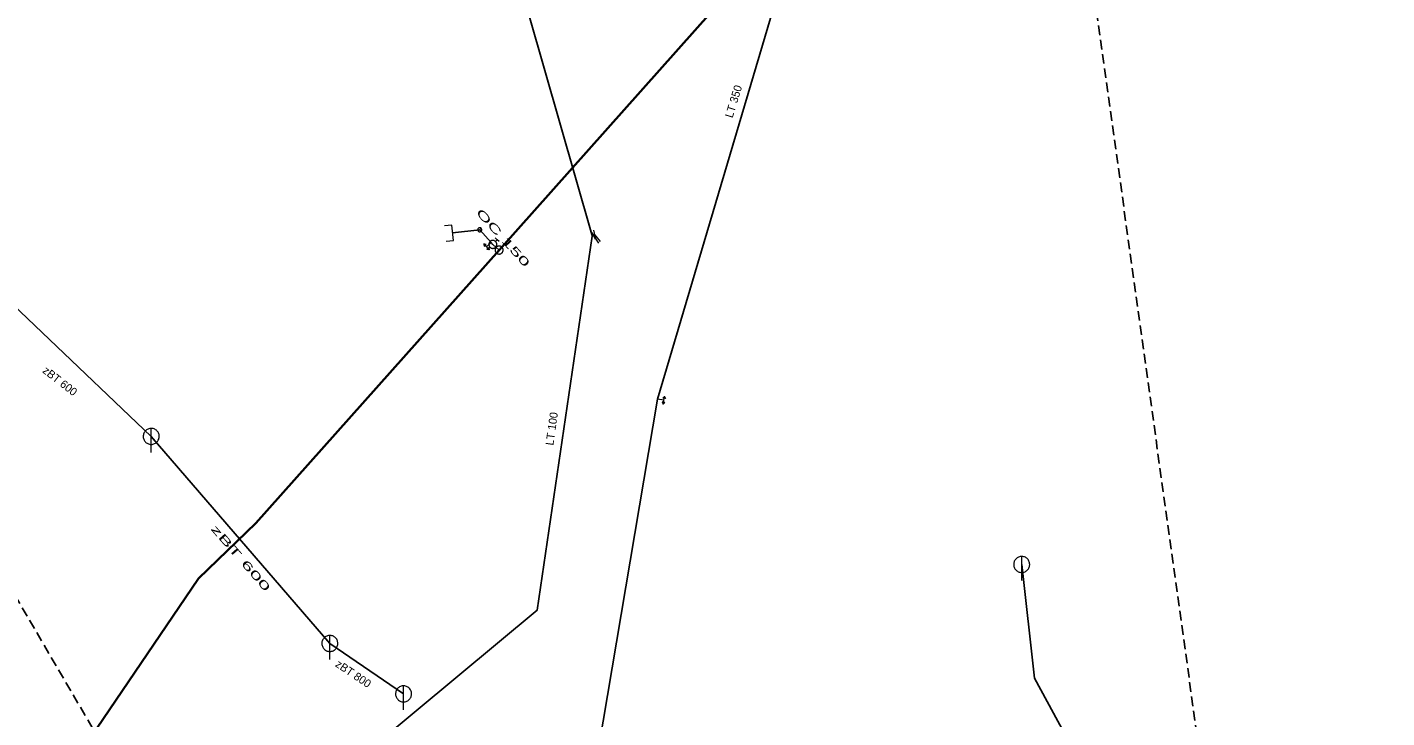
# Model space of a CAD drawing. Extents: x -687016 to -686065, y -974192 to -973552.
# Drawn here: x -686248.4 to -686078.5, y -973940.5 to -973854.3 of the extents above; entities that cross this region are included whole.
import ezdxf

# ---------------------------------------------------------------- set-up
doc = ezdxf.new("R2010")
doc.units = 0
doc.header["$LTSCALE"] = 0.4
doc.linetypes.add('MEDIUM_DASHED', pattern=[4.5, 3, -1.5])
doc.layers.add('1', color=7, linetype='Continuous')
for name, color, linetype, lineweight in [('13', 7, 'Continuous', 13), ('14', 7, 'Continuous', 25), ('17', 7, 'Continuous', 25), ('22', 7, 'Continuous', 13), ('23', 7, 'Continuous', 13), ('34', 7, 'Continuous', 13), ('42', 7, 'Continuous', 13), ('47', 7, 'Continuous', 13), ('63', 7, 'MEDIUM_DASHED', 25)]:
    doc.layers.add(name, color=color, linetype=linetype, lineweight=lineweight)

msp = doc.modelspace()

# ---------------------------------------------------------------- linework, layer by layer
at = {"layer": '13'}
for p, q in [((-686177.649, -973880.329), (-686177.02, -973881.28)), ((-686177.539, -973880.129), (-686176.82, -973881.05))]:
    msp.add_line(p, q, dxfattribs=at)
at = {"layer": '14', "lineweight": 13}
for p, q in [((-686177.867, -973880.202), (-686177.539, -973880.129)), ((-686177.797, -973880.398), (-686177.649, -973880.329)), ((-686190.215, -973881.425), (-686190.418, -973881.199))]:
    msp.add_line(p, q, dxfattribs=at)
at = {"layer": '14'}
for p, q in [((-686232.891, -973905.396), (-686251.059, -973888.086)), ((-686210.577, -973931.25), (-686232.891, -973905.396)), ((-686201.369, -973937.547), (-686210.577, -973931.25))]:
    msp.add_line(p, q, dxfattribs=at)
msp.add_lwpolyline([(-686124.153, -973921.386), (-686122.535, -973935.572), (-686106.927, -973964.355)], dxfattribs=at)
at = {"layer": '17'}
for p, q in [((-686147.316, -973825.46), (-686169.64, -973900.75)), ((-686189.43, -973882.125), (-686190.215, -973881.425))]:
    msp.add_line(p, q, dxfattribs=at)
at = {"layer": '17', "lineweight": 35}
for points in [[(-686163.783, -973551.821), (-686169.469, -973574.282), (-686122.999, -973646.384), (-686098.932, -973712.353), (-686078.54, -973769.323), (-686149.348, -973837.164), (-686189.43, -973882.125)], [(-686189.43, -973882.125), (-686219.828, -973916.223), (-686226.999, -973923.155), (-686246.828, -973952.39), (-686262.803, -973979.756), (-686282.183, -974011.51), (-686299.629, -974035.3), (-686327.833, -974075.543), (-686339.475, -974087.052), (-686408.796, -974118.009)]]:
    msp.add_lwpolyline(points, dxfattribs=at)
at = {"layer": '17'}
for points in [[(-686204.755, -973943.783), (-686184.694, -973927.101), (-686177.797, -973880.398), (-686177.867, -973880.202), (-686191.62, -973832.066)], [(-686190.418, -973881.199), (-686191.853, -973879.59), (-686195.24, -973879.96)], [(-686169.64, -973900.75), (-686177.013, -973944.41), (-686197.048, -973943.572), (-686232.018, -974032.331), (-686151.042, -974110.8), (-686189.024, -974153.642), (-686204.782, -974140.962), (-686246.709, -974191.881)]]:
    msp.add_lwpolyline(points, dxfattribs=at)
at = {"layer": '22'}
for p, q in [((-686232.891, -973907.396), (-686232.89, -973904.396)), ((-686124.153, -973923.387), (-686124.152, -973920.387)), ((-686210.577, -973933.25), (-686210.576, -973930.25)), ((-686201.369, -973939.547), (-686201.368, -973936.547))]:
    msp.add_line(p, q, dxfattribs=at)
for points in [[(-686231.891, -973905.396), (-686231.896, -973905.287), (-686231.914, -973905.179), (-686231.944, -973905.073), (-686231.984, -973904.972), (-686232.036, -973904.875), (-686232.098, -973904.785), (-686232.17, -973904.702), (-686232.25, -973904.628), (-686232.338, -973904.562), (-686232.432, -973904.507), (-686232.532, -973904.462), (-686232.637, -973904.429), (-686232.744, -973904.407), (-686232.853, -973904.397), (-686232.963, -973904.399), (-686233.071, -973904.413), (-686233.178, -973904.438), (-686233.281, -973904.475), (-686233.379, -973904.524), (-686233.471, -973904.582), (-686233.557, -973904.651), (-686233.634, -973904.728), (-686233.703, -973904.814), (-686233.762, -973904.906), (-686233.81, -973905.004), (-686233.847, -973905.107), (-686233.873, -973905.214), (-686233.887, -973905.322), (-686233.89, -973905.432), (-686233.88, -973905.541), (-686233.859, -973905.648), (-686233.825, -973905.752), (-686233.781, -973905.852), (-686233.726, -973905.947), (-686233.66, -973906.035), (-686233.586, -973906.115), (-686233.503, -973906.187), (-686233.413, -973906.249), (-686233.317, -973906.301), (-686233.215, -973906.342), (-686233.11, -973906.372), (-686233.002, -973906.39), (-686232.892, -973906.396), (-686232.783, -973906.39), (-686232.675, -973906.372), (-686232.57, -973906.343), (-686232.468, -973906.302), (-686232.371, -973906.25), (-686232.281, -973906.188), (-686232.198, -973906.117), (-686232.123, -973906.037), (-686232.058, -973905.949), (-686232.002, -973905.855), (-686231.958, -973905.755), (-686231.924, -973905.651), (-686231.902, -973905.543), (-686231.892, -973905.434)], [(-686123.153, -973921.387), (-686123.158, -973921.278), (-686123.176, -973921.17), (-686123.206, -973921.064), (-686123.246, -973920.963), (-686123.298, -973920.866), (-686123.36, -973920.776), (-686123.432, -973920.693), (-686123.512, -973920.619), (-686123.6, -973920.553), (-686123.694, -973920.498), (-686123.794, -973920.453), (-686123.899, -973920.42), (-686124.006, -973920.398), (-686124.115, -973920.388), (-686124.225, -973920.39), (-686124.333, -973920.404), (-686124.44, -973920.429), (-686124.543, -973920.466), (-686124.641, -973920.515), (-686124.733, -973920.573), (-686124.819, -973920.642), (-686124.896, -973920.719), (-686124.965, -973920.805), (-686125.024, -973920.897), (-686125.072, -973920.995), (-686125.109, -973921.098), (-686125.135, -973921.205), (-686125.149, -973921.313), (-686125.152, -973921.423), (-686125.142, -973921.532), (-686125.121, -973921.639), (-686125.087, -973921.743), (-686125.043, -973921.843), (-686124.988, -973921.938), (-686124.922, -973922.026), (-686124.848, -973922.106), (-686124.765, -973922.178), (-686124.675, -973922.24), (-686124.579, -973922.292), (-686124.477, -973922.333), (-686124.372, -973922.363), (-686124.264, -973922.381), (-686124.154, -973922.387), (-686124.045, -973922.381), (-686123.937, -973922.363), (-686123.832, -973922.334), (-686123.73, -973922.293), (-686123.633, -973922.241), (-686123.543, -973922.179), (-686123.46, -973922.108), (-686123.385, -973922.028), (-686123.32, -973921.94), (-686123.264, -973921.846), (-686123.22, -973921.746), (-686123.186, -973921.642), (-686123.164, -973921.534), (-686123.154, -973921.425)], [(-686209.577, -973931.25), (-686209.582, -973931.141), (-686209.6, -973931.033), (-686209.63, -973930.927), (-686209.67, -973930.826), (-686209.722, -973930.729), (-686209.784, -973930.639), (-686209.856, -973930.556), (-686209.936, -973930.482), (-686210.024, -973930.416), (-686210.118, -973930.361), (-686210.218, -973930.316), (-686210.323, -973930.283), (-686210.43, -973930.261), (-686210.539, -973930.251), (-686210.649, -973930.253), (-686210.757, -973930.267), (-686210.864, -973930.292), (-686210.967, -973930.329), (-686211.065, -973930.378), (-686211.157, -973930.436), (-686211.243, -973930.505), (-686211.32, -973930.582), (-686211.389, -973930.668), (-686211.448, -973930.76), (-686211.496, -973930.858), (-686211.533, -973930.961), (-686211.559, -973931.068), (-686211.573, -973931.176), (-686211.576, -973931.286), (-686211.566, -973931.395), (-686211.545, -973931.502), (-686211.511, -973931.606), (-686211.467, -973931.706), (-686211.412, -973931.801), (-686211.346, -973931.889), (-686211.272, -973931.969), (-686211.189, -973932.041), (-686211.099, -973932.103), (-686211.003, -973932.155), (-686210.901, -973932.196), (-686210.796, -973932.226), (-686210.688, -973932.244), (-686210.578, -973932.25), (-686210.469, -973932.244), (-686210.361, -973932.226), (-686210.256, -973932.197), (-686210.154, -973932.156), (-686210.057, -973932.104), (-686209.967, -973932.042), (-686209.884, -973931.971), (-686209.809, -973931.891), (-686209.744, -973931.803), (-686209.688, -973931.709), (-686209.644, -973931.609), (-686209.61, -973931.505), (-686209.588, -973931.397), (-686209.578, -973931.288)], [(-686200.369, -973937.547), (-686200.374, -973937.438), (-686200.392, -973937.33), (-686200.422, -973937.224), (-686200.462, -973937.123), (-686200.514, -973937.026), (-686200.576, -973936.936), (-686200.648, -973936.853), (-686200.728, -973936.779), (-686200.816, -973936.713), (-686200.91, -973936.658), (-686201.01, -973936.613), (-686201.115, -973936.58), (-686201.222, -973936.558), (-686201.331, -973936.548), (-686201.441, -973936.55), (-686201.549, -973936.564), (-686201.656, -973936.589), (-686201.759, -973936.626), (-686201.857, -973936.675), (-686201.949, -973936.733), (-686202.035, -973936.802), (-686202.112, -973936.879), (-686202.181, -973936.965), (-686202.24, -973937.057), (-686202.288, -973937.155), (-686202.325, -973937.258), (-686202.351, -973937.365), (-686202.365, -973937.473), (-686202.368, -973937.583), (-686202.358, -973937.692), (-686202.337, -973937.799), (-686202.303, -973937.903), (-686202.259, -973938.003), (-686202.204, -973938.098), (-686202.138, -973938.186), (-686202.064, -973938.266), (-686201.981, -973938.338), (-686201.891, -973938.4), (-686201.795, -973938.452), (-686201.693, -973938.493), (-686201.588, -973938.523), (-686201.48, -973938.541), (-686201.37, -973938.547), (-686201.261, -973938.541), (-686201.153, -973938.523), (-686201.048, -973938.494), (-686200.946, -973938.453), (-686200.849, -973938.401), (-686200.759, -973938.339), (-686200.676, -973938.268), (-686200.601, -973938.188), (-686200.536, -973938.1), (-686200.48, -973938.006), (-686200.436, -973937.906), (-686200.402, -973937.802), (-686200.38, -973937.694), (-686200.37, -973937.585)]]:
    msp.add_lwpolyline(points, close=True, dxfattribs=at)
at = {"layer": '23'}
for p, q in [((-686192.04, -973879.758), (-686191.657, -973879.415)), ((-686189.943, -973880.608), (-686189.688, -973880.835)), ((-686189.873, -973881.043), (-686189.688, -973880.835)), ((-686189.432, -973881.063), (-686189.688, -973880.835))]:
    msp.add_line(p, q, dxfattribs=at)
for points in [[(-686192.018, -973879.401), (-686192.037, -973879.42), (-686192.055, -973879.44), (-686192.069, -973879.461), (-686192.081, -973879.484), (-686192.092, -973879.509), (-686192.098, -973879.535), (-686192.103, -973879.561), (-686192.105, -973879.586), (-686192.104, -973879.613), (-686192.099, -973879.639), (-686192.092, -973879.665), (-686192.084, -973879.689), (-686192.071, -973879.714), (-686192.057, -973879.735), (-686192.041, -973879.755), (-686192.022, -973879.774), (-686192.002, -973879.792), (-686191.981, -973879.806), (-686191.957, -973879.818), (-686191.932, -973879.829), (-686191.907, -973879.835), (-686191.881, -973879.839), (-686191.855, -973879.842), (-686191.829, -973879.84), (-686191.803, -973879.836), (-686191.777, -973879.829), (-686191.752, -973879.821), (-686191.728, -973879.809), (-686191.706, -973879.794), (-686191.686, -973879.778), (-686191.667, -973879.76), (-686191.65, -973879.74), (-686191.635, -973879.718), (-686191.623, -973879.694), (-686191.613, -973879.669), (-686191.607, -973879.644), (-686191.602, -973879.618), (-686191.599, -973879.592), (-686191.601, -973879.566), (-686191.606, -973879.539), (-686191.612, -973879.514), (-686191.621, -973879.488), (-686191.633, -973879.465), (-686191.647, -973879.443), (-686191.663, -973879.423), (-686191.682, -973879.404), (-686191.701, -973879.387), (-686191.724, -973879.372), (-686191.747, -973879.361), (-686191.773, -973879.35), (-686191.798, -973879.343), (-686191.824, -973879.339), (-686191.849, -973879.336), (-686191.876, -973879.338), (-686191.903, -973879.343), (-686191.928, -973879.349), (-686191.953, -973879.358), (-686191.976, -973879.371), (-686191.998, -973879.385)], [(-686189.847, -973881.758), (-686189.814, -973881.716), (-686189.784, -973881.674), (-686189.761, -973881.625), (-686189.743, -973881.578), (-686189.729, -973881.53), (-686189.721, -973881.477), (-686189.72, -973881.426), (-686189.721, -973881.372), (-686189.728, -973881.322), (-686189.743, -973881.272), (-686189.761, -973881.224), (-686189.785, -973881.179), (-686189.813, -973881.133), (-686189.845, -973881.093), (-686189.881, -973881.057), (-686189.921, -973881.025), (-686189.965, -973880.998), (-686190.011, -973880.973), (-686190.059, -973880.954), (-686190.111, -973880.94), (-686190.16, -973880.932), (-686190.214, -973880.929), (-686190.264, -973880.932), (-686190.317, -973880.941), (-686190.367, -973880.953), (-686190.415, -973880.97), (-686190.461, -973880.994), (-686190.506, -973881.022), (-686190.544, -973881.056), (-686190.584, -973881.093), (-686190.616, -973881.133), (-686190.643, -973881.177), (-686190.668, -973881.223), (-686190.687, -973881.271), (-686190.699, -973881.32), (-686190.709, -973881.372), (-686190.71, -973881.423), (-686190.709, -973881.476), (-686190.7, -973881.528), (-686190.686, -973881.577), (-686190.666, -973881.626), (-686190.645, -973881.674), (-686190.617, -973881.715), (-686190.582, -973881.758), (-686190.546, -973881.794), (-686190.506, -973881.825), (-686190.464, -973881.855), (-686190.416, -973881.878), (-686190.368, -973881.896), (-686190.317, -973881.91), (-686190.267, -973881.918), (-686190.214, -973881.921), (-686190.163, -973881.918), (-686190.113, -973881.911), (-686190.062, -973881.896), (-686190.012, -973881.88), (-686189.967, -973881.856), (-686189.924, -973881.826), (-686189.883, -973881.794)]]:
    msp.add_lwpolyline(points, close=True, dxfattribs=at)
at = {"layer": '34'}
for p, q in [((-686177.859, -973879.875), (-686177.439, -973880.783)), ((-686177.647, -973879.64), (-686177.431, -973880.617)), ((-686191.342, -973881.389), (-686191.318, -973881.368)), ((-686191.334, -973881.421), (-686191.287, -973881.378)), ((-686191.332, -973881.451), (-686191.256, -973881.383)), ((-686191.328, -973881.479), (-686191.229, -973881.389)), ((-686191.321, -973881.51), (-686191.198, -973881.398)), ((-686191.318, -973881.538), (-686191.172, -973881.405)), ((-686191.312, -973881.566), (-686191.144, -973881.412)), ((-686191.311, -973881.598), (-686191.113, -973881.417)), ((-686191.304, -973881.628), (-686191.083, -973881.427)), ((-686191.015, -973881.731), (-686190.418, -973881.199)), ((-686190.945, -973882.031), (-686190.72, -973881.834)), ((-686190.916, -973882.041), (-686190.714, -973881.865)), ((-686190.885, -973882.046), (-686190.713, -973881.896)), ((-686190.857, -973882.054), (-686190.709, -973881.925)), ((-686190.83, -973882.061), (-686190.704, -973881.952)), ((-686190.8, -973882.072), (-686190.699, -973881.983)), ((-686190.773, -973882.078), (-686190.696, -973882.011)), ((-686190.742, -973882.083), (-686190.695, -973882.042)), ((-686190.723, -973881.806), (-686190.685, -973882.102)), ((-686190.712, -973882.095), (-686190.688, -973882.074)), ((-686168.85, -973900.883), (-686169.639, -973900.75)), ((-686168.974, -973900.608), (-686168.768, -973900.394)), ((-686168.66, -973900.641), (-686168.955, -973900.588)), ((-686168.671, -973900.612), (-686168.934, -973900.564)), ((-686168.686, -973900.585), (-686168.911, -973900.544)), ((-686168.697, -973900.558), (-686168.891, -973900.523)), ((-686168.709, -973900.532), (-686168.872, -973900.503)), ((-686168.719, -973900.502), (-686168.851, -973900.479)), ((-686168.731, -973900.477), (-686168.831, -973900.459)), ((-686168.746, -973900.45), (-686168.808, -973900.439)), ((-686168.756, -973900.419), (-686168.787, -973900.414)), ((-686168.75, -973901.174), (-686169.046, -973901.127)), ((-686168.769, -973901.198), (-686169.034, -973901.156)), ((-686168.793, -973901.218), (-686169.019, -973901.183)), ((-686168.812, -973901.24), (-686169.007, -973901.209)), ((-686168.832, -973901.26), (-686168.996, -973901.234)), ((-686168.851, -973901.285), (-686168.984, -973901.264)), ((-686168.871, -973901.305), (-686168.972, -973901.289)), ((-686168.894, -973901.326), (-686168.956, -973901.316)), ((-686168.913, -973901.352), (-686168.945, -973901.347))]:
    msp.add_line(p, q, dxfattribs=at)
for points in [[(-686191.345, -973881.361), (-686191.3, -973881.656), (-686191.056, -973881.433)], [(-686191.056, -973881.433), (-686191.345, -973881.361), (-686190.685, -973882.102)], [(-686190.685, -973882.102), (-686190.973, -973882.023), (-686190.723, -973881.806)], [(-686169.057, -973901.101), (-686168.933, -973901.372), (-686168.768, -973900.394)], [(-686168.768, -973900.394), (-686168.648, -973900.667), (-686168.974, -973900.608)], [(-686168.933, -973901.372), (-686168.73, -973901.153), (-686169.057, -973901.101)]]:
    msp.add_lwpolyline(points, dxfattribs=at)
at = {"layer": '42'}
msp.add_lwpolyline([(-686196.03, -973881.018), (-686195.134, -973880.92), (-686195.344, -973878.999), (-686196.24, -973879.097)], dxfattribs=at)
at = {"layer": '47'}
for points in [[(-686189.762, -973882.498), (-686189.721, -973882.53), (-686189.677, -973882.559), (-686189.631, -973882.582), (-686189.582, -973882.601), (-686189.531, -973882.614), (-686189.479, -973882.622), (-686189.427, -973882.624), (-686189.375, -973882.621), (-686189.324, -973882.613), (-686189.273, -973882.599), (-686189.223, -973882.58), (-686189.177, -973882.556), (-686189.134, -973882.528), (-686189.093, -973882.494), (-686189.056, -973882.457), (-686189.024, -973882.416), (-686188.995, -973882.372), (-686188.972, -973882.325), (-686188.953, -973882.277), (-686188.94, -973882.226), (-686188.932, -973882.174), (-686188.93, -973882.121), (-686188.933, -973882.069), (-686188.941, -973882.018), (-686188.955, -973881.968), (-686188.974, -973881.918), (-686188.998, -973881.872), (-686189.026, -973881.829), (-686189.06, -973881.788), (-686189.097, -973881.751), (-686189.138, -973881.719), (-686189.182, -973881.69), (-686189.228, -973881.666), (-686189.277, -973881.648), (-686189.328, -973881.635), (-686189.379, -973881.627), (-686189.432, -973881.624), (-686189.484, -973881.627), (-686189.536, -973881.636), (-686189.586, -973881.65), (-686189.636, -973881.669), (-686189.682, -973881.692), (-686189.725, -973881.721), (-686189.766, -973881.755), (-686189.803, -973881.792), (-686189.835, -973881.833), (-686189.864, -973881.877), (-686189.887, -973881.923), (-686189.906, -973881.972), (-686189.919, -973882.023), (-686189.927, -973882.074), (-686189.929, -973882.126), (-686189.926, -973882.179), (-686189.918, -973882.23), (-686189.904, -973882.281), (-686189.885, -973882.331), (-686189.861, -973882.376), (-686189.833, -973882.42), (-686189.799, -973882.461)], [(-686189.484, -973882.186), (-686189.477, -973882.192), (-686189.47, -973882.196), (-686189.463, -973882.199), (-686189.455, -973882.202), (-686189.446, -973882.205), (-686189.438, -973882.206), (-686189.429, -973882.207), (-686189.421, -973882.206), (-686189.412, -973882.204), (-686189.404, -973882.202), (-686189.395, -973882.199), (-686189.388, -973882.195), (-686189.381, -973882.19), (-686189.374, -973882.186), (-686189.368, -973882.179), (-686189.362, -973882.172), (-686189.358, -973882.165), (-686189.355, -973882.158), (-686189.352, -973882.15), (-686189.349, -973882.141), (-686189.348, -973882.133), (-686189.347, -973882.124), (-686189.348, -973882.116), (-686189.349, -973882.106), (-686189.352, -973882.099), (-686189.355, -973882.09), (-686189.359, -973882.083), (-686189.364, -973882.076), (-686189.368, -973882.069), (-686189.375, -973882.063), (-686189.382, -973882.057), (-686189.389, -973882.053), (-686189.396, -973882.05), (-686189.404, -973882.047), (-686189.413, -973882.044), (-686189.421, -973882.043), (-686189.43, -973882.042), (-686189.438, -973882.043), (-686189.448, -973882.044), (-686189.455, -973882.047), (-686189.464, -973882.05), (-686189.471, -973882.054), (-686189.478, -973882.059), (-686189.485, -973882.063), (-686189.491, -973882.07), (-686189.497, -973882.077), (-686189.501, -973882.084), (-686189.504, -973882.091), (-686189.507, -973882.099), (-686189.51, -973882.108), (-686189.511, -973882.116), (-686189.512, -973882.125), (-686189.511, -973882.133), (-686189.509, -973882.142), (-686189.507, -973882.15), (-686189.504, -973882.159), (-686189.5, -973882.166), (-686189.495, -973882.173), (-686189.491, -973882.18)]]:
    msp.add_lwpolyline(points, close=True, dxfattribs=at)
at = {"layer": '63'}
msp.add_lwpolyline([(-686318.355, -973808.199), (-686197.373, -973790.916), (-686197.373, -973790.916), (-686115.78, -973845.177), (-686115.78, -973845.177), (-686098.497, -973969.777), (-686098.497, -973969.777), (-686210.235, -973993.089), (-686210.235, -973993.089)], close=True, dxfattribs=at)

# ---------------------------------------------------------------- texts
at = {"layer": '1'}
for s, rotation, p in [('LT 350', 73, (-686160.275, -973865.7)), ('zBT 600 ', 322, (-686246.556, -973897.35)), ('LT 100', 82, (-686182.658, -973906.572)), ('zBT 800 ', 326, (-686209.982, -973934.061))]:
    msp.add_text(s, height=1, rotation=rotation, dxfattribs=at).set_placement(p)
for s, rotation, width, p in [('OC 150', 312, 2, (-686192.397, -973877.499)), ('zBT 600 ', 311, 2.1, (-686225.523, -973916.971))]:
    msp.add_text(s, height=1, rotation=rotation, dxfattribs=dict(at, width=width)).set_placement(p)

doc.saveas('drawing.dxf')
